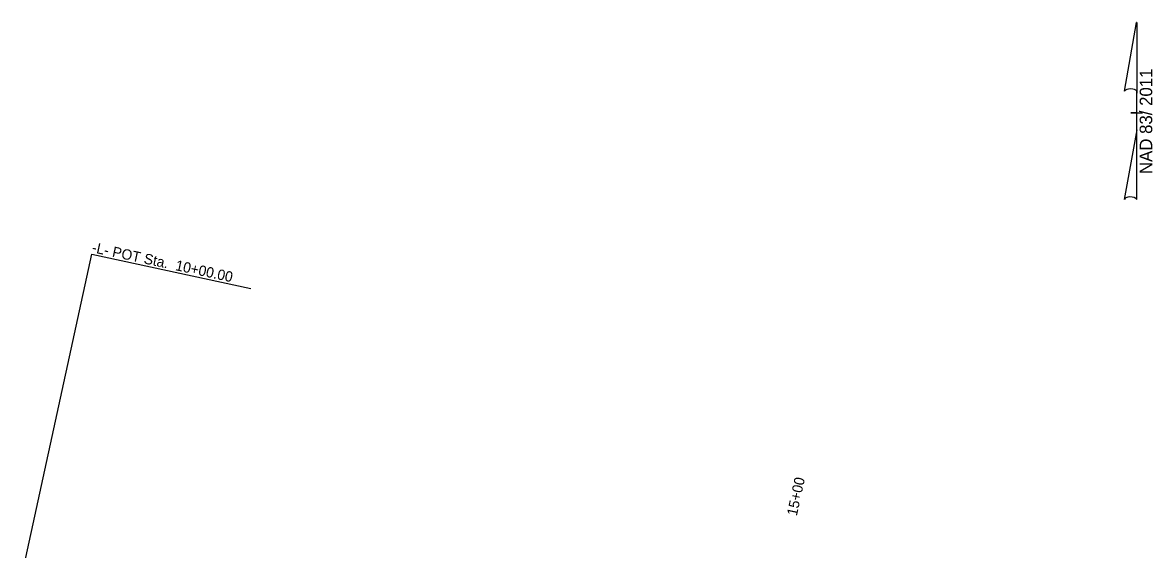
# Model space of a CAD drawing. Extents: x 1762196 to 1766326, y 709922 to 713142.
# Drawn here: x 1762198 to 1762962, y 712785 to 713142 of the extents above; entities that cross this region are included whole.
import ezdxf

# ---------------------------------------------------------------- set-up
doc = ezdxf.new("R2010")
doc.units = 0
for name, color, linetype in [('Prop Horizontal Alignment Station Label', 7, 'Continuous'), ('Prop Horizontal Alignment Tick Label', 7, 'Continuous'), ('Prop North Arrow NAD83 for Plan Sheets CELL', 7, 'Continuous')]:
    doc.layers.add(name, color=color, linetype=linetype)

msp = doc.modelspace()

# ---------------------------------------------------------------- linework, layer by layer
at = {"layer": 'Prop Horizontal Alignment Station Label'}
for p, q in [((1762197.86, 712769.43), (1762244.63, 712985.01)), ((1762244.63, 712985.01), (1762352.24, 712961.87))]:
    msp.add_line(p, q, dxfattribs=at)
at = {"layer": 'Prop North Arrow NAD83 for Plan Sheets CELL'}
for p, q in [((1762943.26, 713095.54), (1762951.46, 713141.89)), ((1762951.51, 713141.89), (1762951.46, 713141.89)), ((1762951.51, 713141.89), (1762951.46, 713141.89)), ((1762951.51, 713141.89), (1762951.51, 713094.09)), ((1762951.51, 713069.29), (1762951.51, 713095.49)), ((1762951.51, 713094.09), (1762951.51, 713095.44)), ((1762947.51, 713080.89), (1762947.46, 713080.89)), ((1762951.06, 713080.89), (1762947.51, 713080.89)), ((1762947.56, 713080.89), (1762955.56, 713080.89)), ((1762951.51, 713069.29), (1762943.16, 713022.04)), ((1762951.56, 713022.24), (1762951.51, 713069.29))]:
    msp.add_line(p, q, dxfattribs=at)
for centre, start_param, end_param in [((1762947.4, 713095.05), 0.216388, 2.908219), ((1762947.4, 713021.88), 0.201328, 3.141593)]:
    msp.add_ellipse(centre, major_axis=(4.23, -0.03), ratio=0.461098, start_param=start_param, end_param=end_param, dxfattribs=at)

# ---------------------------------------------------------------- texts
at = {"layer": 'Prop Horizontal Alignment Station Label'}
msp.add_text('-L- POT Sta.  10+00.00', height=7, rotation=347.86385, dxfattribs=at).set_placement((1762244.34, 712986.5))
at = {"layer": 'Prop Horizontal Alignment Tick Label'}
msp.add_text('15+00', height=7, rotation=77.75984, dxfattribs=at).set_placement((1762721.6, 712807.56))
at = {"layer": 'Prop North Arrow NAD83 for Plan Sheets CELL'}
msp.add_text('NAD 83/ 2011', height=8.5, rotation=90, dxfattribs=at).set_placement((1762962.03, 713039.37))

doc.saveas('drawing.dxf')
